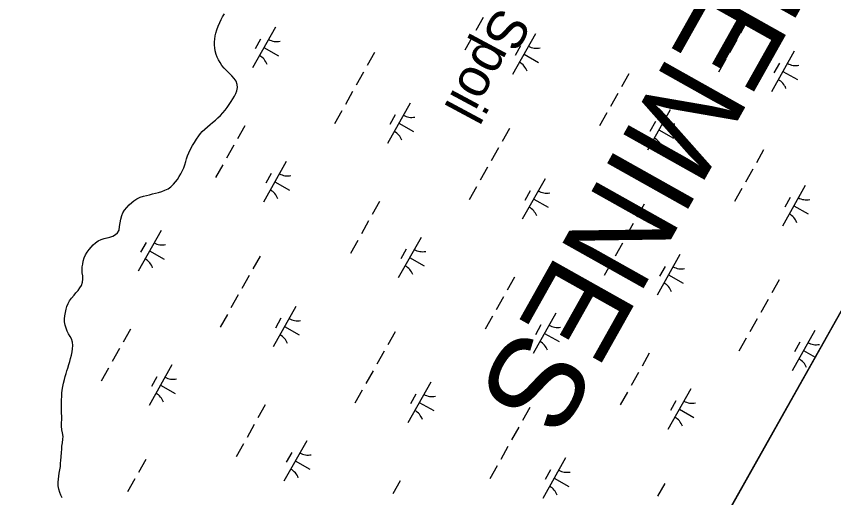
# Model space of a CAD drawing. Extents: x 3913936 to 3933962, y 195330 to 217741.
# Drawn here: x 3927207 to 3928086, y 203147 to 203665 of the extents above; entities that cross this region are included whole.
import ezdxf

# ---------------------------------------------------------------- set-up
doc = ezdxf.new("R2010")
doc.units = 0
for name, color, linetype in [('V-GRID-FRAM', 7, 'Continuous'), ('V-RIVR-IDEN', 7, 'Continuous'), ('V-TOPO-GNAM-IDEN', 7, 'Continuous'), ('V-TOPO-SHOR', 7, 'Continuous'), ('V-WETL-SWMP', 7, 'Continuous')]:
    doc.layers.add(name, color=color, linetype=linetype)

msp = doc.modelspace()

# ---------------------------------------------------------------- linework, layer by layer
at = {"layer": 'V-GRID-FRAM'}
msp.add_lwpolyline([(3932010.33, 210314.99), (3924440.13, 196848.23), (3917917.56, 202110.57), (3924798.65, 214359.02), (3932010.33, 210314.99)], dxfattribs=at)
at = {"layer": 'V-TOPO-SHOR'}
for points in [[(3927433.64, 203566.45), (3927435.96, 203569.74), (3927438.11, 203573.02), (3927439.92, 203575.88), (3927441.63, 203578.81), (3927443, 203581.58), (3927444.12, 203584.52), (3927444.71, 203587.97), (3927444.45, 203591.51), (3927443.49, 203594.88), (3927441.41, 203597.89), (3927438.81, 203600.56), (3927436.56, 203602.8), (3927433.27, 203605.89), (3927430.42, 203608.99), (3927428.08, 203611.92), (3927426.08, 203614.85), (3927424.44, 203617.87), (3927423.13, 203620.88), (3927422.09, 203623.73), (3927421.04, 203627.52), (3927420.43, 203630.63), (3927420.08, 203633.74), (3927420.15, 203637.1), (3927420.4, 203640.12), (3927420.91, 203643.75), (3927421.68, 203646.69), (3927422.71, 203650.23), (3927423.99, 203653.94), (3927425.79, 203658.01), (3927427.25, 203661.29), (3927428.88, 203664.23), (3927430.94, 203667.34)], [(3927265.48, 203296.69), (3927266.42, 203300.41), (3927267.1, 203303.77), (3927267.61, 203307.06), (3927267.77, 203310.68), (3927267.51, 203314.22), (3927266.46, 203317.76), (3927265.07, 203320.43), (3927263.34, 203323.1), (3927261.86, 203326.11), (3927260.56, 203329.13), (3927259.51, 203332.41), (3927258.9, 203336.03), (3927258.8, 203339.4), (3927259.14, 203342.59), (3927259.91, 203346.05), (3927260.67, 203349.59), (3927261.53, 203352.61), (3927262.81, 203355.89), (3927264.36, 203358.57), (3927266.51, 203361.51), (3927269.26, 203364.89), (3927271.16, 203367.22), (3927273.48, 203369.9), (3927275.45, 203372.59), (3927277.09, 203375.27), (3927278.2, 203378.72), (3927278.62, 203381.83), (3927278.61, 203385.46), (3927278, 203388.65), (3927277.73, 203392.18), (3927277.9, 203395.21), (3927278.58, 203398.14), (3927279.08, 203401.43), (3927279.85, 203404.96), (3927281.31, 203408.16), (3927283.12, 203411.1), (3927285.44, 203413.96), (3927287.5, 203416.38), (3927289.83, 203418.8), (3927292.32, 203421.05), (3927295.08, 203423.05), (3927298.35, 203424.61), (3927301.46, 203425.65), (3927304.56, 203426.27), (3927307.67, 203427.05), (3927310.77, 203428.18), (3927313.71, 203429.92), (3927315.94, 203431.99), (3927317.66, 203434.85), (3927318.17, 203438.48), (3927318.67, 203442.62), (3927319.27, 203446.5), (3927320.46, 203450.39), (3927321.75, 203453.24), (3927323.47, 203456.18), (3927325.97, 203459.21), (3927328.29, 203461.81), (3927331.13, 203464.4), (3927333.54, 203466.4), (3927336.55, 203468.3), (3927340.09, 203470.04), (3927343.8, 203471.17), (3927347.16, 203472.05), (3927350.35, 203472.74), (3927353.54, 203473.62), (3927356.56, 203474.32), (3927359.84, 203475.27), (3927363.38, 203476.32), (3927366.74, 203477.54), (3927370.27, 203479.27), (3927373.37, 203481.44), (3927376.13, 203484.12), (3927378.36, 203486.63), (3927380.34, 203489.31), (3927382.23, 203492.34), (3927383.87, 203495.11), (3927385.41, 203498.04), (3927387.04, 203501.59), (3927388.33, 203504.87), (3927389.35, 203508.41), (3927390.21, 203511.35), (3927391.06, 203514.46), (3927392.43, 203517.92), (3927394.41, 203521.98), (3927396.47, 203525.61), (3927398.53, 203528.89), (3927400.85, 203532.61), (3927403.26, 203535.99), (3927405.06, 203538.49), (3927407.04, 203540.83), (3927409.71, 203543.34), (3927412.55, 203545.77), (3927415.48, 203548.19), (3927418.15, 203550.35), (3927421.16, 203552.95), (3927423.75, 203555.46), (3927426.67, 203558.15), (3927429.08, 203560.83), (3927431.49, 203563.68), (3927433.64, 203566.45)], [(3927256.49, 203146.92), (3927255.1, 203149.76), (3927253.8, 203152.61), (3927252.67, 203156.14), (3927252.14, 203159.77), (3927252.04, 203163.56), (3927252.38, 203166.84), (3927252.71, 203170.04), (3927253.23, 203173.23), (3927253.91, 203176.77), (3927254.5, 203180.4), (3927254.66, 203183.94), (3927255, 203186.96), (3927255.25, 203191.02), (3927255.49, 203195.68), (3927255.91, 203199.31), (3927256.17, 203202.33), (3927256.67, 203205.95), (3927257.18, 203209.75), (3927257.34, 203212.86), (3927256.56, 203216.57), (3927256.12, 203219.76), (3927255.67, 203223.73), (3927255.75, 203227.36), (3927255.83, 203231.07), (3927255.82, 203234.35), (3927255.63, 203238.06), (3927255.62, 203241.51), (3927255.62, 203244.53), (3927255.6, 203248.42), (3927255.68, 203251.78), (3927255.84, 203256.01), (3927256.09, 203259.38), (3927256.51, 203262.66), (3927257.19, 203266.72), (3927257.96, 203270.17), (3927258.73, 203273.97), (3927259.49, 203277.17), (3927260.52, 203280.62), (3927261.55, 203283.48), (3927262.49, 203286.41), (3927263.69, 203290.21), (3927264.63, 203293.5), (3927265.48, 203296.69)]]:
    msp.add_lwpolyline(points, dxfattribs=at)
at = {"layer": 'V-WETL-SWMP'}
for p, q in [((3928459.34, 203998.07), (3927708.67, 202662.7)), ((3927428.88, 203664.23), (3927430.94, 203667.34)), ((3927423.99, 203653.94), (3927425.79, 203658.01)), ((3927425.79, 203658.01), (3927427.25, 203661.29)), ((3927427.25, 203661.29), (3927428.88, 203664.23)), ((3927708.89, 203663.3), (3927701.05, 203649.36)), ((3927993.43, 203660.47), (3927985.59, 203646.52)), ((3927421.68, 203646.69), (3927422.71, 203650.23)), ((3927422.71, 203650.23), (3927423.99, 203653.94)), ((3927485.63, 203652.96), (3927461.13, 203609.38)), ((3927420.4, 203640.12), (3927420.91, 203643.75)), ((3927420.91, 203643.75), (3927421.68, 203646.69)), ((3927697.13, 203642.38), (3927689.29, 203628.44)), ((3927765.23, 203645.74), (3927740.73, 203602.16)), ((3927420.08, 203633.74), (3927420.15, 203637.1)), ((3927420.43, 203630.63), (3927420.08, 203633.74)), ((3927420.15, 203637.1), (3927420.4, 203640.12)), ((3927469.59, 203640.18), (3927463.71, 203629.72)), ((3927749.2, 203632.96), (3927743.32, 203622.5)), ((3927981.67, 203639.54), (3927973.83, 203625.6)), ((3927421.04, 203627.52), (3927420.43, 203630.63)), ((3927422.09, 203623.73), (3927421.04, 203627.52)), ((3927423.13, 203620.88), (3927422.09, 203623.73)), ((3927473.38, 203631.17), (3927489.07, 203622.35)), ((3927592.22, 203625.65), (3927584.38, 203611.7)), ((3927752.98, 203623.95), (3927768.67, 203615.13)), ((3928043.6, 203627.19), (3928019.1, 203583.61)), ((3927424.44, 203617.87), (3927423.13, 203620.88)), ((3927426.08, 203614.85), (3927424.44, 203617.87)), ((3927428.08, 203611.92), (3927426.08, 203614.85)), ((3927969.91, 203618.62), (3927962.07, 203604.68)), ((3928027.56, 203614.41), (3928021.68, 203603.95)), ((3927430.42, 203608.99), (3927428.08, 203611.92)), ((3927433.27, 203605.89), (3927430.42, 203608.99)), ((3927436.56, 203602.8), (3927433.27, 203605.89)), ((3928031.35, 203605.4), (3928047.04, 203596.58)), ((3927438.81, 203600.56), (3927436.56, 203602.8)), ((3927441.41, 203597.89), (3927438.81, 203600.56)), ((3927443.49, 203594.88), (3927441.41, 203597.89)), ((3927580.46, 203604.72), (3927572.62, 203590.78)), ((3927865.65, 203602.72), (3927857.81, 203588.77)), ((3927444.45, 203591.51), (3927443.49, 203594.88)), ((3927444.12, 203584.52), (3927444.71, 203587.97)), ((3927444.71, 203587.97), (3927444.45, 203591.51)), ((3927439.92, 203575.88), (3927441.63, 203578.81)), ((3927441.63, 203578.81), (3927443.01, 203581.58)), ((3927443.01, 203581.58), (3927444.12, 203584.52)), ((3927568.7, 203583.8), (3927560.86, 203569.86)), ((3927853.89, 203581.8), (3927846.05, 203567.85)), ((3927435.96, 203569.74), (3927438.11, 203573.02)), ((3927438.11, 203573.02), (3927439.92, 203575.88)), ((3927630.63, 203571.45), (3927606.13, 203527.87)), ((3927429.08, 203560.83), (3927431.49, 203563.68)), ((3927431.49, 203563.68), (3927433.64, 203566.45)), ((3927433.64, 203566.45), (3927435.96, 203569.74)), ((3927556.94, 203562.88), (3927549.1, 203548.94)), ((3927910.23, 203564.23), (3927885.73, 203520.65)), ((3927418.15, 203550.35), (3927421.16, 203552.95)), ((3927421.16, 203552.95), (3927423.75, 203555.46)), ((3927423.75, 203555.46), (3927426.67, 203558.15)), ((3927426.67, 203558.15), (3927429.08, 203560.83)), ((3927614.59, 203558.67), (3927608.71, 203548.21)), ((3927842.13, 203560.87), (3927834.29, 203546.93)), ((3927409.71, 203543.34), (3927412.55, 203545.76)), ((3927412.55, 203545.76), (3927415.48, 203548.19)), ((3927415.48, 203548.19), (3927418.15, 203550.35)), ((3927452.68, 203546.98), (3927444.84, 203533.03)), ((3927618.38, 203549.66), (3927634.07, 203540.84)), ((3927737.22, 203544.14), (3927729.38, 203530.19)), ((3927894.19, 203551.45), (3927888.31, 203540.99)), ((3927400.85, 203532.61), (3927403.26, 203535.99)), ((3927403.26, 203535.99), (3927405.06, 203538.49)), ((3927405.06, 203538.49), (3927407.04, 203540.83)), ((3927407.04, 203540.83), (3927409.71, 203543.34)), ((3927897.98, 203542.44), (3927913.67, 203533.62)), ((3927396.47, 203525.61), (3927398.53, 203528.89)), ((3927398.53, 203528.89), (3927400.85, 203532.61)), ((3927440.92, 203526.06), (3927433.08, 203512.11)), ((3927391.06, 203514.46), (3927392.43, 203517.91)), ((3927392.43, 203517.91), (3927394.41, 203521.98)), ((3927394.41, 203521.98), (3927396.47, 203525.61)), ((3927725.46, 203523.22), (3927717.62, 203509.27)), ((3928010.65, 203521.21), (3928002.81, 203507.26)), ((3927389.35, 203508.41), (3927390.21, 203511.35)), ((3927390.21, 203511.35), (3927391.06, 203514.46)), ((3927497.26, 203508.49), (3927472.76, 203464.91)), ((3927385.41, 203498.04), (3927387.04, 203501.59)), ((3927387.04, 203501.59), (3927388.33, 203504.87)), ((3927388.33, 203504.87), (3927389.35, 203508.41)), ((3927429.16, 203505.13), (3927421.32, 203491.19)), ((3927713.7, 203502.29), (3927705.86, 203488.35)), ((3927998.89, 203500.29), (3927991.05, 203486.34)), ((3927380.34, 203489.31), (3927382.23, 203492.34)), ((3927382.23, 203492.34), (3927383.87, 203495.11)), ((3927383.87, 203495.11), (3927385.41, 203498.04)), ((3927481.22, 203495.71), (3927475.34, 203485.25)), ((3927373.37, 203481.44), (3927376.13, 203484.12)), ((3927376.13, 203484.12), (3927378.37, 203486.63)), ((3927378.37, 203486.63), (3927380.34, 203489.31)), ((3927485.01, 203486.7), (3927500.7, 203477.88)), ((3927775.63, 203489.94), (3927751.13, 203446.36)), ((3928055.23, 203482.72), (3928030.73, 203439.14)), ((3927350.35, 203472.74), (3927353.54, 203473.62)), ((3927353.54, 203473.62), (3927356.56, 203474.31)), ((3927356.56, 203474.31), (3927359.84, 203475.27)), ((3927359.84, 203475.27), (3927363.38, 203476.32)), ((3927363.38, 203476.32), (3927366.74, 203477.54)), ((3927366.74, 203477.54), (3927370.27, 203479.27)), ((3927370.27, 203479.27), (3927373.37, 203481.44)), ((3927701.94, 203481.37), (3927694.1, 203467.43)), ((3927759.59, 203477.16), (3927753.71, 203466.7)), ((3927987.13, 203479.37), (3927979.29, 203465.42)), ((3927331.13, 203464.4), (3927333.54, 203466.4)), ((3927333.54, 203466.4), (3927336.56, 203468.3)), ((3927336.56, 203468.3), (3927340.09, 203470.04)), ((3927340.09, 203470.04), (3927343.8, 203471.17)), ((3927343.8, 203471.17), (3927347.16, 203472.04)), ((3927347.16, 203472.04), (3927350.35, 203472.74)), ((3927597.68, 203465.47), (3927589.84, 203451.52)), ((3927763.38, 203468.15), (3927779.07, 203459.33)), ((3928039.19, 203469.94), (3928033.31, 203459.48)), ((3927321.75, 203453.24), (3927323.47, 203456.18)), ((3927323.47, 203456.18), (3927325.97, 203459.21)), ((3927325.97, 203459.21), (3927328.29, 203461.81)), ((3927328.29, 203461.81), (3927331.13, 203464.4)), ((3927882.22, 203462.63), (3927874.38, 203448.68)), ((3928042.98, 203460.93), (3928058.67, 203452.11)), ((3927319.27, 203446.5), (3927320.46, 203450.39)), ((3927320.46, 203450.39), (3927321.75, 203453.24)), ((3927317.66, 203434.85), (3927318.17, 203438.48)), ((3927318.17, 203438.48), (3927318.67, 203442.62)), ((3927318.67, 203442.62), (3927319.27, 203446.5)), ((3927585.92, 203444.55), (3927578.08, 203430.6)), ((3927870.46, 203441.71), (3927862.62, 203427.76)), ((3927310.77, 203428.18), (3927313.7, 203429.92)), ((3927313.7, 203429.92), (3927315.94, 203431.99)), ((3927315.94, 203431.99), (3927317.66, 203434.85)), ((3927362.66, 203434.2), (3927338.16, 203390.62)), ((3927289.83, 203418.8), (3927292.32, 203421.05)), ((3927292.32, 203421.05), (3927295.08, 203423.05)), ((3927295.08, 203423.05), (3927298.35, 203424.61)), ((3927298.35, 203424.61), (3927301.46, 203425.65)), ((3927301.46, 203425.65), (3927304.57, 203426.27)), ((3927304.57, 203426.27), (3927307.67, 203427.05)), ((3927307.67, 203427.05), (3927310.77, 203428.18)), ((3927346.62, 203421.42), (3927340.74, 203410.96)), ((3927574.16, 203423.62), (3927566.32, 203409.68)), ((3927642.26, 203426.98), (3927617.76, 203383.4)), ((3927858.7, 203420.79), (3927850.86, 203406.84)), ((3927283.12, 203411.1), (3927285.44, 203413.96)), ((3927285.44, 203413.96), (3927287.5, 203416.38)), ((3927287.5, 203416.38), (3927289.83, 203418.8)), ((3927350.41, 203412.41), (3927366.1, 203403.59)), ((3927626.22, 203414.2), (3927620.34, 203403.74)), ((3927279.09, 203401.42), (3927279.85, 203404.96)), ((3927279.85, 203404.96), (3927281.31, 203408.16)), ((3927281.31, 203408.16), (3927283.12, 203411.1)), ((3927469.25, 203406.89), (3927461.41, 203392.94)), ((3927630.01, 203405.19), (3927645.7, 203396.37)), ((3927920.62, 203408.43), (3927896.12, 203364.85)), ((3927277.73, 203392.19), (3927277.9, 203395.21)), ((3927277.9, 203395.21), (3927278.58, 203398.14)), ((3927278.58, 203398.14), (3927279.09, 203401.42)), ((3927846.94, 203399.86), (3927839.1, 203385.92)), ((3927904.59, 203395.65), (3927898.71, 203385.19)), ((3927278, 203388.65), (3927277.73, 203392.19)), ((3927278.61, 203385.46), (3927278, 203388.65)), ((3927278.62, 203381.83), (3927278.61, 203385.46)), ((3927457.49, 203385.97), (3927449.65, 203372.02)), ((3927908.37, 203386.64), (3927924.06, 203377.82)), ((3927277.09, 203375.27), (3927278.2, 203378.72)), ((3927278.2, 203378.72), (3927278.62, 203381.83)), ((3927742.68, 203383.96), (3927734.84, 203370.01)), ((3928027.22, 203381.12), (3928019.38, 203367.17)), ((3927271.16, 203367.22), (3927273.48, 203369.9)), ((3927273.48, 203369.9), (3927275.46, 203372.59)), ((3927275.46, 203372.59), (3927277.09, 203375.27)), ((3927264.36, 203358.57), (3927266.51, 203361.51)), ((3927266.51, 203361.51), (3927269.26, 203364.89)), ((3927269.26, 203364.89), (3927271.16, 203367.22)), ((3927445.73, 203365.04), (3927437.89, 203351.1)), ((3927730.92, 203363.04), (3927723.08, 203349.09)), ((3928015.46, 203360.2), (3928007.62, 203346.25)), ((3927260.67, 203349.59), (3927261.53, 203352.61)), ((3927261.53, 203352.61), (3927262.81, 203355.89)), ((3927262.81, 203355.89), (3927264.36, 203358.57)), ((3927507.66, 203352.69), (3927483.15, 203309.11)), ((3927258.8, 203339.4), (3927259.14, 203342.59)), ((3927259.14, 203342.59), (3927259.91, 203346.05)), ((3927259.91, 203346.05), (3927260.67, 203349.59)), ((3927433.97, 203344.12), (3927426.13, 203330.18)), ((3927719.16, 203342.12), (3927711.32, 203328.17)), ((3927787.26, 203345.47), (3927762.76, 203301.89)), ((3927258.9, 203336.03), (3927258.8, 203339.4)), ((3927259.51, 203332.41), (3927258.9, 203336.03)), ((3927491.62, 203339.91), (3927485.74, 203329.45)), ((3927771.22, 203332.69), (3927765.34, 203322.23)), ((3928003.7, 203339.28), (3927995.85, 203325.33)), ((3927260.56, 203329.13), (3927259.51, 203332.41)), ((3927261.86, 203326.11), (3927260.56, 203329.13)), ((3927263.34, 203323.1), (3927261.86, 203326.11)), ((3927329.71, 203328.22), (3927321.87, 203314.27)), ((3927495.4, 203330.9), (3927511.1, 203322.08)), ((3927614.25, 203325.38), (3927606.41, 203311.43)), ((3928065.62, 203326.92), (3928041.12, 203283.34)), ((3927265.07, 203320.43), (3927263.34, 203323.1)), ((3927266.46, 203317.75), (3927265.07, 203320.43)), ((3927267.51, 203314.22), (3927266.46, 203317.75)), ((3927775.01, 203323.68), (3927790.7, 203314.86)), ((3927991.93, 203318.36), (3927984.09, 203304.41)), ((3927267.1, 203303.77), (3927267.61, 203307.05)), ((3927267.77, 203310.68), (3927267.51, 203314.22)), ((3927267.61, 203307.05), (3927267.77, 203310.68)), ((3927317.95, 203307.3), (3927310.11, 203293.35)), ((3928049.59, 203314.14), (3928043.71, 203303.68)), ((3927265.48, 203296.69), (3927266.42, 203300.4)), ((3927266.42, 203300.4), (3927267.1, 203303.77)), ((3927602.49, 203304.46), (3927594.65, 203290.51)), ((3927887.68, 203302.45), (3927879.84, 203288.5)), ((3928053.37, 203305.13), (3928065.86, 203298.11)), ((3927262.49, 203286.41), (3927263.69, 203290.21)), ((3927263.69, 203290.21), (3927264.63, 203293.49)), ((3927264.63, 203293.49), (3927265.48, 203296.69)), ((3927374.29, 203289.73), (3927349.79, 203246.15)), ((3927259.5, 203277.17), (3927260.52, 203280.62)), ((3927260.52, 203280.62), (3927261.55, 203283.48)), ((3927261.55, 203283.48), (3927262.49, 203286.41)), ((3927306.19, 203286.38), (3927298.35, 203272.43)), ((3927590.73, 203283.54), (3927582.89, 203269.59)), ((3927875.92, 203281.53), (3927868.08, 203267.58)), ((3927257.96, 203270.17), (3927258.73, 203273.97)), ((3927258.73, 203273.97), (3927259.5, 203277.17)), ((3927358.25, 203276.95), (3927352.37, 203266.49)), ((3927652.65, 203271.18), (3927628.15, 203227.6)), ((3927256.09, 203259.38), (3927256.51, 203262.66)), ((3927256.51, 203262.66), (3927257.19, 203266.72)), ((3927257.19, 203266.72), (3927257.96, 203270.17)), ((3927362.04, 203267.94), (3927377.73, 203259.12)), ((3927578.97, 203262.61), (3927571.13, 203248.67)), ((3927932.25, 203263.96), (3927907.75, 203220.38)), ((3927255.68, 203251.78), (3927255.84, 203256.01)), ((3927255.84, 203256.01), (3927256.09, 203259.38)), ((3927636.62, 203258.4), (3927630.74, 203247.94)), ((3927864.16, 203260.61), (3927856.32, 203246.66)), ((3927255.6, 203248.42), (3927255.68, 203251.78)), ((3927255.62, 203244.53), (3927255.6, 203248.42)), ((3927474.71, 203246.71), (3927466.87, 203232.76)), ((3927640.4, 203249.39), (3927656.09, 203240.57)), ((3927916.22, 203251.18), (3927910.34, 203240.72)), ((3927255.62, 203241.51), (3927255.62, 203244.53)), ((3927255.63, 203238.06), (3927255.62, 203241.51)), ((3927255.82, 203234.35), (3927255.63, 203238.06)), ((3927759.25, 203243.87), (3927751.4, 203229.92)), ((3927920, 203242.17), (3927935.69, 203233.35)), ((3927255.67, 203223.73), (3927255.75, 203227.36)), ((3927255.75, 203227.36), (3927255.83, 203231.07)), ((3927255.83, 203231.07), (3927255.82, 203234.35)), ((3927256.12, 203219.76), (3927255.67, 203223.73)), ((3927256.56, 203216.57), (3927256.12, 203219.76)), ((3927462.95, 203225.79), (3927455.11, 203211.84)), ((3927747.48, 203222.95), (3927739.64, 203209)), ((3927257.34, 203212.86), (3927256.56, 203216.57)), ((3927256.67, 203205.95), (3927257.18, 203209.75)), ((3927257.18, 203209.75), (3927257.34, 203212.86)), ((3927255.91, 203199.31), (3927256.17, 203202.33)), ((3927256.17, 203202.33), (3927256.67, 203205.95)), ((3927451.19, 203204.87), (3927443.35, 203190.92)), ((3927519.29, 203208.22), (3927494.78, 203164.64)), ((3927735.72, 203202.03), (3927727.88, 203188.08)), ((3927255.25, 203191.02), (3927255.49, 203195.68)), ((3927255.49, 203195.68), (3927255.91, 203199.31)), ((3927503.25, 203195.44), (3927497.37, 203184.98)), ((3927254.5, 203180.4), (3927254.66, 203183.94)), ((3927254.66, 203183.94), (3927255, 203186.96)), ((3927255, 203186.96), (3927255.25, 203191.02)), ((3927346.28, 203188.13), (3927338.44, 203174.18)), ((3927507.03, 203186.43), (3927522.73, 203177.61)), ((3927797.65, 203189.67), (3927773.15, 203146.09)), ((3927253.23, 203173.23), (3927253.91, 203176.77)), ((3927253.91, 203176.77), (3927254.5, 203180.4)), ((3927723.96, 203181.11), (3927716.12, 203167.16)), ((3927781.62, 203176.89), (3927775.73, 203166.43)), ((3927252.04, 203163.56), (3927252.38, 203166.84)), ((3927252.38, 203166.84), (3927252.72, 203170.04)), ((3927252.72, 203170.04), (3927253.23, 203173.23)), ((3927334.52, 203167.21), (3927326.68, 203153.26)), ((3927785.4, 203167.88), (3927801.09, 203159.06)), ((3927252.14, 203159.77), (3927252.04, 203163.56)), ((3927252.67, 203156.14), (3927252.14, 203159.77)), ((3927619.71, 203165.2), (3927611.87, 203151.25)), ((3927904.24, 203162.36), (3927896.4, 203148.41)), ((3927253.8, 203152.61), (3927252.67, 203156.14)), ((3927255.1, 203149.76), (3927253.8, 203152.61)), ((3927256.49, 203146.92), (3927255.1, 203149.76))]:
    msp.add_line(p, q, dxfattribs=at)
for centre, start, end in [((3927487.12, 203655.13), 239.88608, 281.42974), ((3927766.72, 203647.91), 239.88608, 281.42974), ((3927460.05, 203606.97), 19.88608, 61.42973), ((3927739.65, 203599.75), 19.88608, 61.42973), ((3928045.09, 203629.36), 239.88608, 281.42974), ((3928018.02, 203581.2), 19.88608, 61.42973), ((3927632.12, 203573.62), 239.88608, 281.42974), ((3927911.72, 203566.4), 239.88608, 281.42974), ((3927605.05, 203525.46), 19.88608, 61.42973), ((3927884.65, 203518.25), 19.88608, 61.42973), ((3927498.75, 203510.66), 239.88608, 281.42974), ((3927471.68, 203462.5), 19.88608, 61.42973), ((3927777.12, 203492.11), 239.88608, 281.42974), ((3928056.72, 203484.89), 239.88608, 281.42974), ((3927750.05, 203443.96), 19.88608, 61.42973), ((3928029.65, 203436.74), 19.88608, 61.42973), ((3927364.15, 203436.37), 239.88608, 281.42974), ((3927643.75, 203429.15), 239.88608, 281.42974), ((3927337.08, 203388.21), 19.88608, 61.42973), ((3927616.68, 203381), 19.88608, 61.42973), ((3927922.12, 203410.6), 239.88608, 281.42974), ((3927895.05, 203362.45), 19.88608, 61.42973), ((3927509.15, 203354.86), 239.88608, 281.42974), ((3927788.75, 203347.64), 239.88608, 281.42974), ((3927482.08, 203306.71), 19.88608, 61.42973), ((3927761.68, 203299.49), 19.88608, 61.42973), ((3928067.11, 203329.09), 239.88608, 281.42974), ((3928040.04, 203280.94), 19.88608, 61.42973), ((3927375.78, 203291.9), 239.88608, 281.42974), ((3927348.71, 203243.75), 19.88608, 61.42973), ((3927654.14, 203273.35), 239.88608, 281.42974), ((3927933.75, 203266.13), 239.88608, 281.42974), ((3927627.07, 203225.2), 19.88608, 61.42973), ((3927906.68, 203217.98), 19.88608, 61.42973), ((3927520.78, 203210.39), 239.88608, 281.42974), ((3927493.71, 203162.24), 19.88608, 61.42973), ((3927799.14, 203191.84), 239.88608, 281.42974), ((3927772.07, 203143.69), 19.88608, 61.42973)]:
    msp.add_arc(centre, 17.62, start, end, dxfattribs=at)

# ---------------------------------------------------------------- texts
at = {"layer": 'V-RIVR-IDEN'}
msp.add_text('Spoil', height=42, rotation=241.7834, dxfattribs=at).set_placement((3927725.13, 203676.5))
at = {"layer": 'V-TOPO-GNAM-IDEN'}
msp.add_text('PLAQUEMINES', height=99.9998, rotation=240.68438, dxfattribs=at).set_placement((3928174.67, 204098.47))

doc.saveas('drawing.dxf')
